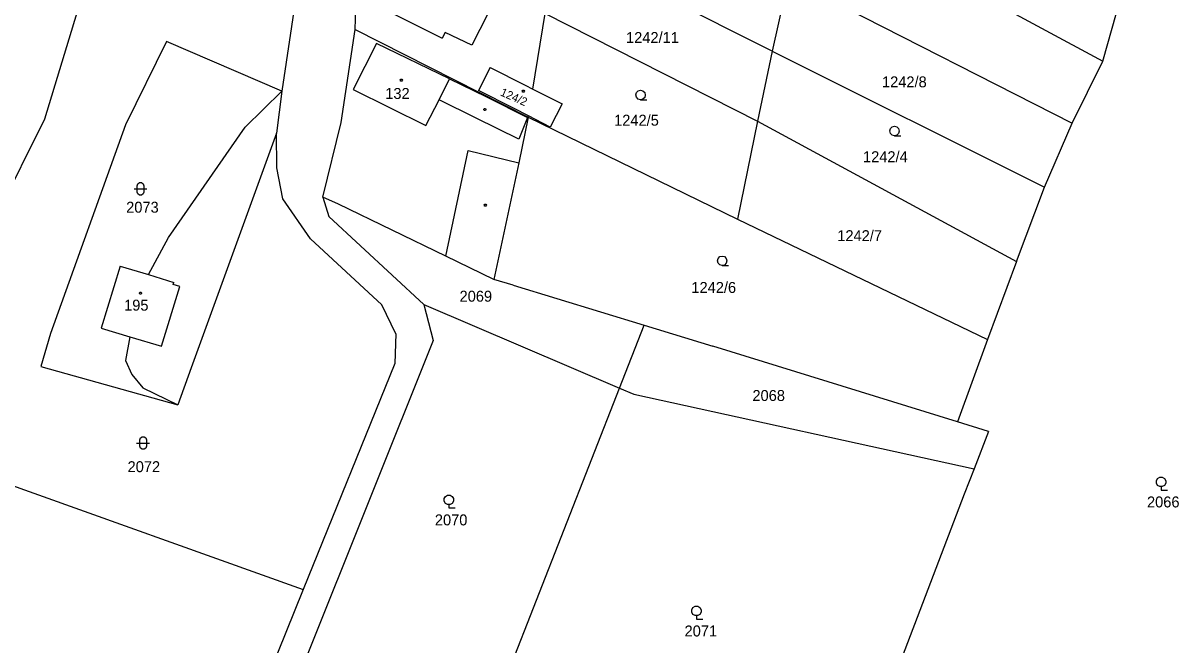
# Model space of a CAD drawing. Extents: x -802857 to -799647, y -1020285 to -1015884.
# Drawn here: x -801407 to -801227.4, y -1018091.1 to -1017994.4 of the extents above; entities that cross this region are included whole.
import ezdxf

# ---------------------------------------------------------------- set-up
doc = ezdxf.new("R2010")
doc.units = 0
for name, color, linetype in [('Default', 7, 'Continuous'), ('KN_HRANICE', 7, 'Continuous'), ('KN_KULTURY', 7, 'Continuous'), ('KN_PARCELY', 7, 'Continuous'), ('KN_SLUCKY', 7, 'Continuous')]:
    doc.layers.add(name, color=color, linetype=linetype)

# ---------------------------------------------------------------- blocks, each defined once
blk = doc.blocks.new('304')
at = {"layer": 'Default'}
blk.add_lwpolyline([(0, 0), (-0.38, 0.1), (-0.65, 0.37), (-0.75, 0.74), (-0.65, 1.11), (-0.38, 1.38), (-0.01, 1.48), (0.36, 1.38), (0.63, 1.11), (0.73, 0.73), (0.63, 0.35), (0.36, 0.08), (-0.02, -0.02), (0.98, -0.02)], dxfattribs=at)
blk = doc.blocks.new('305')
at = {"layer": 'Default'}
blk.add_lwpolyline([(0, 0.53), (-0.19, 0.53), (-0.53, 0.72), (-0.72, 1.06), (-0.72, 1.45), (-0.53, 1.79), (-0.19, 1.98), (0.2, 1.98), (0.54, 1.79), (0.73, 1.45), (0.73, 1.06), (0.54, 0.72), (0.2, 0.53), (0.01, 0.53), (0.01, 0), (1.01, 0)], dxfattribs=at)
blk = doc.blocks.new('316')
at = {"layer": 'Default'}
for points in [[(-0.5, 1.5), (-0.4, 1.79), (-0.15, 1.97), (0.16, 1.97), (0.41, 1.79), (0.51, 1.5), (0.51, 0.5), (0.41, 0.21), (0.16, 0.03), (-0.15, 0.03), (-0.4, 0.21), (-0.5, 0.5), (-0.5, 1.5)], [(-1, 1), (0.27, 1), (1, 1)]]:
    blk.add_lwpolyline(points, dxfattribs=at)
blk = doc.blocks.new('402')
at = {"layer": 'Default'}
blk.add_lwpolyline([(0.09, 0.15), (0.18, 0), (0.09, -0.15), (-0.09, -0.15), (-0.18, 0), (-0.09, 0.15), (0.09, 0.15)], dxfattribs=at)

msp = doc.modelspace()

# ---------------------------------------------------------------- linework, layer by layer
at = {"layer": 'KN_HRANICE'}
for p, q in [((-801283.17, -1017976.65), (-801239.16, -1018000.38)), ((-801396.64, -1017986.09), (-801403.7, -1018009.39)), ((-801290.6, -1017998.81), (-801315.64, -1017986.18)), ((-801239.16, -1018000.38), (-801235.44, -1017987.03)), ((-801288.02, -1017987.5), (-801290.6, -1017998.81)), ((-801288.02, -1017987.5), (-801243.96, -1018010)), ((-801364.52, -1017989.8), (-801366.8, -1018005.03)), ((-801355.39, -1017995.42), (-801355.23, -1017989.94)), ((-801327.78, -1018004.7), (-801325.88, -1017992.98)), ((-801325.88, -1017992.98), (-801292.85, -1018009.68)), ((-801357.6, -1018009.88), (-801355.39, -1017995.42)), ((-801355.39, -1017995.42), (-801328.49, -1018009.09)), ((-801384.72, -1017997.28), (-801391.12, -1018010.28)), ((-801366.8, -1018005.03), (-801384.72, -1017997.28)), ((-801290.6, -1017998.81), (-801292.85, -1018009.68)), ((-801290.6, -1017998.81), (-801248.25, -1018019.94)), ((-801334.42, -1018001.35), (-801336.22, -1018004.93)), ((-801334.42, -1018001.35), (-801328.98, -1018004.1)), ((-801243.96, -1018010), (-801239.16, -1018000.38)), ((-801372.53, -1018010.6), (-801366.8, -1018005.03)), ((-801366.8, -1018005.03), (-801367.65, -1018011.57)), ((-801330.78, -1018007.67), (-801336.22, -1018004.93)), ((-801328.98, -1018004.1), (-801327.78, -1018004.7)), ((-801327.78, -1018004.7), (-801323.22, -1018006.97)), ((-801323.22, -1018006.97), (-801325.07, -1018010.63)), ((-801328.46, -1018008.88), (-801330.78, -1018007.67)), ((-801403.7, -1018009.39), (-801421.73, -1018045.46)), ((-801391.12, -1018010.28), (-801402.79, -1018042.66)), ((-801360.46, -1018021.5), (-801357.6, -1018009.88)), ((-801328.49, -1018009.09), (-801329.99, -1018016.14)), ((-801328.49, -1018009.09), (-801328.46, -1018008.88)), ((-801328.49, -1018009.09), (-801295.95, -1018024.91)), ((-801325.07, -1018010.63), (-801328.46, -1018008.88)), ((-801292.85, -1018009.68), (-801295.95, -1018024.91)), ((-801292.85, -1018009.68), (-801252.58, -1018031.49)), ((-801248.25, -1018019.94), (-801243.96, -1018010)), ((-801384.44, -1018027.77), (-801372.53, -1018010.6)), ((-801367.65, -1018011.57), (-801380.88, -1018048.02)), ((-801367.61, -1018016.94), (-801367.65, -1018011.57)), ((-801366.63, -1018021.76), (-801367.61, -1018016.94)), ((-801329.99, -1018016.14), (-801333.87, -1018034.28)), ((-801252.58, -1018031.49), (-801248.25, -1018019.94)), ((-801362.36, -1018027.96), (-801366.63, -1018021.76)), ((-801358.01, -1018022.56), (-801360.46, -1018021.5)), ((-801360.46, -1018021.5), (-801359.5, -1018024.48)), ((-801341.29, -1018030.67), (-801358.01, -1018022.56)), ((-801359.5, -1018024.48), (-801344.72, -1018038.17)), ((-801295.95, -1018024.91), (-801257.13, -1018043.64)), ((-801387.54, -1018033.54), (-801384.44, -1018027.77)), ((-801362.36, -1018027.96), (-801351.25, -1018038.21)), ((-801333.87, -1018034.28), (-801341.29, -1018030.67)), ((-801252.58, -1018031.49), (-801257.13, -1018043.64)), ((-801391.96, -1018032.2), (-801394.91, -1018041.83)), ((-801391.96, -1018032.2), (-801387.54, -1018033.54)), ((-801330.84, -1018035.16), (-801333.87, -1018034.28)), ((-801330.84, -1018035.16), (-801310.46, -1018041.38)), ((-801349.1, -1018042.73), (-801351.25, -1018038.21)), ((-801344.72, -1018038.17), (-801343.28, -1018043.75)), ((-801344.72, -1018038.17), (-801314.3, -1018051.18)), ((-801402.79, -1018042.66), (-801404.28, -1018047.83)), ((-801394.91, -1018041.83), (-801390.42, -1018043.18)), ((-801349.1, -1018042.73), (-801349.23, -1018047.34)), ((-801314.3, -1018051.18), (-801310.46, -1018041.38)), ((-801310.46, -1018041.38), (-801299.8, -1018044.64)), ((-801390.42, -1018043.18), (-801391.12, -1018046.89)), ((-801343.28, -1018043.75), (-801363.17, -1018093.47)), ((-801261.78, -1018056.41), (-801299.8, -1018044.64)), ((-801257.13, -1018043.64), (-801261.78, -1018056.41)), ((-801404.28, -1018047.83), (-801382.99, -1018053.78)), ((-801391.12, -1018046.89), (-801390.14, -1018049.06)), ((-801380.88, -1018048.02), (-801382.99, -1018053.78)), ((-801349.23, -1018047.34), (-801363.47, -1018082.46)), ((-801390.14, -1018049.06), (-801388.4, -1018051.14)), ((-801388.4, -1018051.14), (-801382.99, -1018053.78)), ((-801336.64, -1018108.15), (-801314.3, -1018051.18)), ((-801314.3, -1018051.18), (-801312.07, -1018052.13)), ((-801312.07, -1018052.13), (-801259.2, -1018063.73)), ((-801256.96, -1018057.9), (-801261.78, -1018056.41)), ((-801256.96, -1018057.9), (-801259.2, -1018063.73)), ((-801426.55, -1018059.97), (-801363.47, -1018082.46)), ((-801259.2, -1018063.73), (-801260.71, -1018067.67)), ((-801260.71, -1018067.67), (-801284.83, -1018130.58)), ((-801363.47, -1018082.46), (-801367.49, -1018092.36))]:
    msp.add_line(p, q, dxfattribs=at)
at = {"layer": 'KN_SLUCKY'}
for p, q in [((-801333.33, -1017990.11), (-801337.28, -1017997.9)), ((-801349.97, -1017992.75), (-801345.71, -1017994.87)), ((-801345.71, -1017994.87), (-801341.88, -1017996.78)), ((-801341.42, -1017995.92), (-801341.88, -1017996.78)), ((-801337.28, -1017997.9), (-801341.42, -1017995.92)), ((-801352.07, -1017997.62), (-801355.72, -1018004.74)), ((-801340.74, -1018003.13), (-801352.07, -1017997.62)), ((-801342.37, -1018006.35), (-801340.74, -1018003.13)), ((-801340.74, -1018003.13), (-801334.97, -1018005.93)), ((-801355.72, -1018004.74), (-801344.44, -1018010.35)), ((-801344.44, -1018010.35), (-801342.37, -1018006.35)), ((-801336.6, -1018009.2), (-801342.37, -1018006.35)), ((-801334.97, -1018005.93), (-801328.64, -1018009.13)), ((-801329.97, -1018012.48), (-801336.6, -1018009.2)), ((-801328.64, -1018009.13), (-801329.97, -1018012.48)), ((-801341.29, -1018030.67), (-801337.84, -1018014.22)), ((-801337.84, -1018014.22), (-801329.99, -1018016.14)), ((-801387.54, -1018033.54), (-801383.6, -1018034.74)), ((-801385.54, -1018044.65), (-801382.66, -1018035.4)), ((-801383.69, -1018035.05), (-801383.6, -1018034.74)), ((-801382.66, -1018035.4), (-801383.69, -1018035.05)), ((-801390.42, -1018043.18), (-801385.54, -1018044.65))]:
    msp.add_line(p, q, dxfattribs=at)

# ---------------------------------------------------------------- block references
at = {"layer": 'KN_KULTURY'}
for name, p in [('402', (-801348.24, -1018003.31)), ('402', (-801329.26, -1018005.04)), ('304', (-801311.03, -1018006.35)), ('402', (-801335.25, -1018007.87)), ('304', (-801271.56, -1018011.95)), ('316', (-801388.79, -1018021.21)), ('402', (-801335.16, -1018022.76)), ('304', (-801298.35, -1018032.12)), ('402', (-801388.78, -1018036.43)), ('316', (-801388.38, -1018060.71)), ('305', (-801230.13, -1018067.01)), ('305', (-801340.85, -1018069.8)), ('305', (-801302.36, -1018087.06))]:
    msp.add_blockref(name, p, dxfattribs=at)

# ---------------------------------------------------------------- texts
at = {"layer": 'KN_PARCELY'}
for s, p in [('1242/11', (-801313.3, -1017997.54)), ('1242/8', (-801273.51, -1018004.43)), ('132', (-801350.73, -1018006.23)), ('1242/5', (-801315.15, -1018010.39)), ('1242/4', (-801276.46, -1018016.06)), ('2073', (-801391.01, -1018023.91)), ('1242/7', (-801280.46, -1018028.33)), ('1242/6', (-801303.14, -1018036.38)), ('195', (-801391.33, -1018039.13)), ('2069', (-801339.18, -1018037.74)), ('2068', (-801293.65, -1018053.17)), ('2072', (-801390.79, -1018064.23)), ('2066', (-801232.31, -1018069.71)), ('2070', (-801343.02, -1018072.5)), ('2071', (-801304.2, -1018089.76))]:
    msp.add_text(s, height=1.7, dxfattribs=at).set_placement(p)
msp.add_text('124/2', height=1.29, rotation=336.269, dxfattribs=at).set_placement((-801332.96, -1018005.65))

doc.saveas('drawing.dxf')
